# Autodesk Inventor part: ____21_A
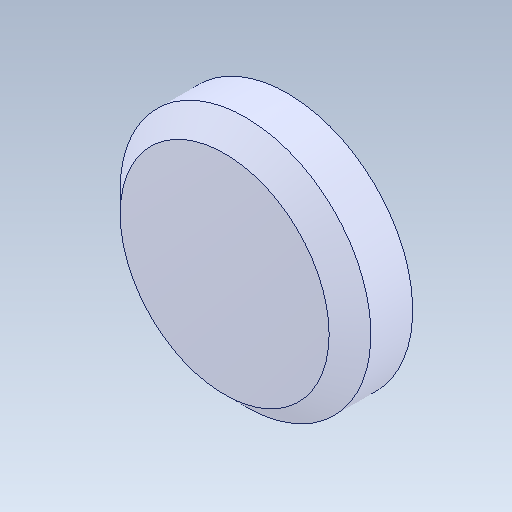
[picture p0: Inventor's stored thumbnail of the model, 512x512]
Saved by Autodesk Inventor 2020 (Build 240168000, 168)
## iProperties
Created: 2017-09
Part Number: ____21_A
Material: Générique
Document SubType Name: Modeling
Designer: bruno
Density: 1 g/cm^3
Appearance: Par défaut
Author: bruno
Sending System: SolidWorks 2016
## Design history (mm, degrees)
feature "Importée1"
node "Solide1"
